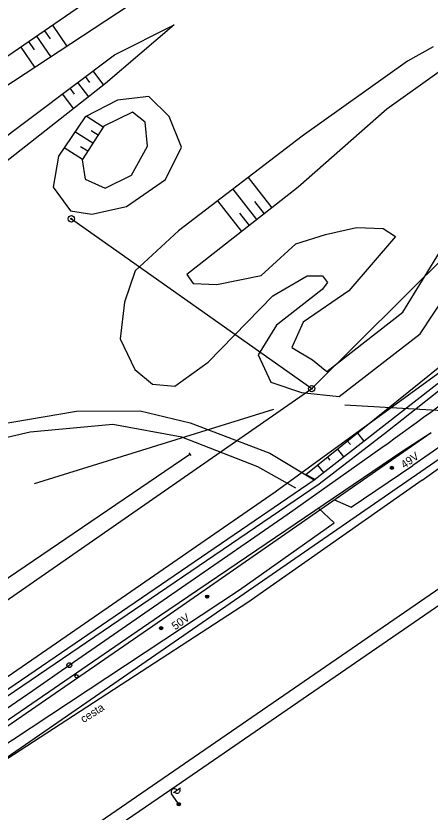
# Model space of a CAD drawing. Extents: x -469926 to -462499, y -1098642 to -1092733.
# Drawn here: x -466191.4 to -466126.7, y -1095960.6 to -1095836.3 of the extents above; entities that cross this region are included whole.
import ezdxf

# ---------------------------------------------------------------- set-up
doc = ezdxf.new("R2010")
doc.units = 0
for name, color, linetype in [('Vrstva 1', 7, 'Continuous'), ('Vrstva 10', 7, 'Continuous'), ('Vrstva 11', 7, 'Continuous'), ('Vrstva 13', 7, 'Continuous'), ('Vrstva 14', 7, 'Continuous'), ('Vrstva 24', 7, 'Continuous'), ('Vrstva 44', 7, 'Continuous'), ('Vrstva 48', 7, 'Continuous'), ('Vrstva 50', 7, 'Continuous'), ('Vrstva 6', 7, 'Continuous'), ('Vrstva 62', 7, 'Continuous'), ('Vrstva 8', 7, 'Continuous')]:
    doc.layers.add(name, color=color, linetype=linetype)

msp = doc.modelspace()

# ---------------------------------------------------------------- linework, layer by layer
at = {"layer": 'Vrstva 1'}
for p, q in [((-466145.15, -1095894.51), (-466082.34, -1095832.11)), ((-466145.15, -1095894.51), (-466082.34, -1095832.11)), ((-466182.7, -1095867.99), (-466145.15, -1095894.51)), ((-466207.82, -1095937.97), (-466145.15, -1095894.51)), ((-466207.82, -1095937.97), (-466145.15, -1095894.51))]:
    msp.add_line(p, q, dxfattribs=at)
for points in [[(-466210.14, -1095956.35), (-466188.73, -1095941.65), (-466183.02, -1095937.7), (-466170.53, -1095929.08), (-466148.98, -1095914.16), (-466134.33, -1095903.79)], [(-466724.57, -1096293.52), (-466714.37, -1096286.02), (-466704.21, -1096278.54), (-466695.06, -1096271.86), (-466685.62, -1096264.93), (-466671.16, -1096254.3), (-466659.11, -1096245.39), (-466634.9, -1096227.39), (-466620.02, -1096216.8), (-466602.98, -1096205), (-466568.99, -1096181.57), (-466522.69, -1096149.63), (-466496.45, -1096131.58), (-466439.19, -1096092.1), (-466394.38, -1096061.36), (-466347.94, -1096029.73), (-466315.43, -1096007.55), (-466259.5, -1095969.51), (-466164.18, -1095904.72)], [(-466200.77, -1095977.65), (-466186.05, -1095967.51), (-466178.22, -1095962.11), (-466097.13, -1095906.36)]]:
    msp.add_lwpolyline(points, dxfattribs=at)
msp.add_arc((-466398.56, -1095531.02), 456.92, 305.3291, 310.8345, dxfattribs=at)
at = {"layer": 'Vrstva 10'}
for p, q in [((-466101.5, -1095899.39), (-466139.97, -1095897.07)), ((-466188.47, -1095909.3), (-466151.05, -1095897.72))]:
    msp.add_line(p, q, dxfattribs=at)
for points in [[(-466169.44, -1095826.6), (-466206.83, -1095852.3), (-466241.68, -1095876.03), (-466204.38, -1095854.75), (-466166.51, -1095829.87)], [(-466257.17, -1095903.36), (-466258.01, -1095899), (-466253.85, -1095896.13), (-466249.92, -1095895.89), (-466243.68, -1095892.52), (-466216.94, -1095871.66), (-466195.35, -1095856.9), (-466175.95, -1095842.35), (-466166.66, -1095837.7), (-466177.39, -1095846.87), (-466196.94, -1095862.23), (-466215.42, -1095875.35), (-466231.4, -1095889.92), (-466244.34, -1095900.39), (-466247.67, -1095900.85), (-466250.08, -1095900.27), (-466252.75, -1095902), (-466255.04, -1095904.92)], [(-466185.67, -1095837.75), (-466183.44, -1095840.99)], [(-466186.91, -1095838.6), (-466186.02, -1095839.89)], [(-466189.38, -1095840.3), (-466188.51, -1095841.57)], [(-466188.14, -1095839.45), (-466185.95, -1095842.64)], [(-466190.61, -1095841.15), (-466188.46, -1095844.29)], [(-466179.33, -1095844.88), (-466177.67, -1095847.09)], [(-466180.53, -1095845.78), (-466179.86, -1095846.68)], [(-466182.92, -1095847.58), (-466182.24, -1095848.5)], [(-466181.73, -1095846.68), (-466180.03, -1095848.94)], [(-466184.12, -1095848.48), (-466182.39, -1095850.79)], [(-466177.72, -1095853.65), (-466180.39, -1095851.95)], [(-466179.34, -1095856.18), (-466182.14, -1095854.39)], [(-466178.53, -1095854.91), (-466179.6, -1095854.23)], [(-466180.95, -1095858.71), (-466183.81, -1095856.88)], [(-466180.14, -1095857.44), (-466181.26, -1095856.73)]]:
    msp.add_lwpolyline(points, dxfattribs=at)
at = {"layer": 'Vrstva 11'}
for p, q in [((-466132.86, -1095906.97), (-466132.54, -1095906.65)), ((-466132.73, -1095907.1), (-466132.41, -1095906.78)), ((-466161.72, -1095927.08), (-466161.39, -1095926.75)), ((-466161.59, -1095927.21), (-466161.26, -1095926.88)), ((-466168.91, -1095932.01), (-466168.59, -1095931.69)), ((-466168.78, -1095932.15), (-466168.46, -1095931.82))]:
    msp.add_line(p, q, dxfattribs=at)
for centre in [(-466132.63, -1095906.88), (-466161.48, -1095926.99), (-466168.68, -1095931.92)]:
    msp.add_circle(centre, 0.25, dxfattribs=at)
at = {"layer": 'Vrstva 13'}
for points in [[(-466000, -1095814.27), (-466009.79, -1095826.38), (-466022.25, -1095837.46), (-466044.21, -1095854.09), (-466061.58, -1095865.63), (-466069.9, -1095872.3), (-466072.6, -1095875.22), (-466084.54, -1095879.16), (-466099.65, -1095886.96), (-466116.56, -1095897.64), (-466129.35, -1095906.52)], [(-466127.89, -1095908.79), (-466114.73, -1095899.39), (-466097.6, -1095888.4), (-466082.79, -1095881.69), (-466077.6, -1095881.25), (-466073.44, -1095879.76), (-466077.1, -1095886.28), (-466075.51, -1095891.49)], [(-466127.89, -1095908.79), (-466114.73, -1095899.39), (-466097.6, -1095888.4), (-466082.79, -1095881.69), (-466077.6, -1095881.25), (-466073.44, -1095879.76), (-466077.1, -1095886.28), (-466075.51, -1095891.49)], [(-466374.19, -1096000), (-466332.05, -1095971.44), (-466298.9, -1095947.61), (-466243.94, -1095910.08), (-466240.17, -1095907.94), (-466235.57, -1095906.87), (-466228.22, -1095905.61), (-466216.23, -1095905.01), (-466194.51, -1095900.15), (-466181.92, -1095898.03), (-466171.97, -1095897.98), (-466164.14, -1095899.83), (-466151.71, -1095904.6), (-466144.76, -1095908.73)], [(-466147.65, -1095910.07), (-466153.55, -1095906.72), (-466165.44, -1095902.07), (-466176.22, -1095900.11), (-466189.12, -1095901.31), (-466205.11, -1095904.98), (-466217.1, -1095907.41), (-466223.08, -1095908.19), (-466229.62, -1095908.34), (-466235.8, -1095909.2), (-466240.59, -1095910.65), (-466246.26, -1095914.17), (-466297.93, -1095949.87), (-466329.85, -1095972.98), (-466369.94, -1096000)], [(-466141.59, -1095911.87), (-466138.97, -1095913.04), (-466129.35, -1095906.52)], [(-466141.59, -1095911.87), (-466138.97, -1095913.04), (-466129.35, -1095906.52)], [(-466141.59, -1095911.87), (-466138.97, -1095913.04), (-466129.35, -1095906.52)], [(-466127.89, -1095908.79), (-466155.15, -1095927.91), (-466196.99, -1095955.1), (-466229.43, -1095978.52)], [(-466230.73, -1095976.53), (-466197.96, -1095953.3), (-466156.42, -1095925.93), (-466141.63, -1095915.46), (-466144.1, -1095913.18)]]:
    msp.add_lwpolyline(points, dxfattribs=at)
at = {"layer": 'Vrstva 14'}
msp.add_circle((-466181.9, -1095939.43), 0.25, dxfattribs=at)
msp.add_circle((-466181.9, -1095939.43), 0.25, dxfattribs=at)
msp.add_circle((-466181.9, -1095939.43), 0.25, dxfattribs=at)
at = {"layer": 'Vrstva 24'}
for centre, radius in [((-466182.7, -1095867.99), 0.5), ((-466182.7, -1095867.99), 0.1), ((-466145.15, -1095894.51), 0.5), ((-466145.15, -1095894.51), 0.5), ((-466145.15, -1095894.51), 0.1), ((-466145.15, -1095894.51), 0.1)]:
    msp.add_circle(centre, radius, dxfattribs=at)
at = {"layer": 'Vrstva 44'}
for p, q in [((-466150.88, -1095910.6), (-466120.73, -1095888.71)), ((-466150.88, -1095910.6), (-466120.73, -1095888.71)), ((-466185.03, -1095934.22), (-466150.88, -1095910.6)), ((-466185.03, -1095934.22), (-466150.88, -1095910.6)), ((-466185.03, -1095934.22), (-466150.88, -1095910.6)), ((-466267.43, -1095990.87), (-466185.03, -1095934.22))]:
    msp.add_line(p, q, dxfattribs=at)
at = {"layer": 'Vrstva 48'}
for p, q in [((-466138, -1095901.45), (-466137, -1095902.69)), ((-466138, -1095901.45), (-466137, -1095902.69)), ((-466138, -1095901.45), (-466137, -1095902.69)), ((-466139.56, -1095902.7), (-466139.11, -1095903.25)), ((-466139.56, -1095902.7), (-466139.11, -1095903.25)), ((-466139.56, -1095902.7), (-466139.11, -1095903.25)), ((-466141.12, -1095903.96), (-466140.16, -1095905.15)), ((-466141.12, -1095903.96), (-466140.16, -1095905.15)), ((-466141.12, -1095903.96), (-466140.16, -1095905.15)), ((-466142.67, -1095905.21), (-466142.29, -1095905.69)), ((-466142.67, -1095905.21), (-466142.29, -1095905.69)), ((-466142.67, -1095905.21), (-466142.29, -1095905.69)), ((-466144.23, -1095906.47), (-466143.31, -1095907.6)), ((-466144.23, -1095906.47), (-466143.31, -1095907.6)), ((-466144.23, -1095906.47), (-466143.31, -1095907.6))]:
    msp.add_line(p, q, dxfattribs=at)
for points in [[(-466185.67, -1095837.75), (-466183.44, -1095840.99)], [(-466185.67, -1095837.75), (-466183.44, -1095840.99)], [(-466186.91, -1095838.6), (-466186.02, -1095839.89)], [(-466186.91, -1095838.6), (-466186.02, -1095839.89)], [(-466189.38, -1095840.3), (-466188.51, -1095841.57)], [(-466189.38, -1095840.3), (-466188.51, -1095841.57)], [(-466188.14, -1095839.45), (-466185.95, -1095842.64)], [(-466188.14, -1095839.45), (-466185.95, -1095842.64)], [(-466190.61, -1095841.15), (-466188.46, -1095844.29)], [(-466190.61, -1095841.15), (-466188.46, -1095844.29)], [(-466179.33, -1095844.88), (-466177.67, -1095847.09)], [(-466179.33, -1095844.88), (-466177.67, -1095847.09)], [(-466180.53, -1095845.78), (-466179.86, -1095846.68)], [(-466180.53, -1095845.78), (-466179.86, -1095846.68)], [(-466182.92, -1095847.58), (-466182.24, -1095848.5)], [(-466182.92, -1095847.58), (-466182.24, -1095848.5)], [(-466181.73, -1095846.68), (-466180.03, -1095848.94)], [(-466181.73, -1095846.68), (-466180.03, -1095848.94)], [(-466184.12, -1095848.48), (-466182.39, -1095850.79)], [(-466184.12, -1095848.48), (-466182.39, -1095850.79)], [(-466177.72, -1095853.65), (-466180.39, -1095851.95)], [(-466177.72, -1095853.65), (-466180.39, -1095851.95)], [(-466179.34, -1095856.18), (-466182.14, -1095854.39)], [(-466179.34, -1095856.18), (-466182.14, -1095854.39)], [(-466178.53, -1095854.91), (-466179.6, -1095854.23)], [(-466178.53, -1095854.91), (-466179.6, -1095854.23)], [(-466180.95, -1095858.71), (-466183.81, -1095856.88)], [(-466180.95, -1095858.71), (-466183.81, -1095856.88)], [(-466180.14, -1095857.44), (-466181.26, -1095856.73)], [(-466180.14, -1095857.44), (-466181.26, -1095856.73)], [(-466151.35, -1095866.26), (-466155.04, -1095861.52)], [(-466151.35, -1095866.26), (-466155.04, -1095861.52)], [(-466153.71, -1095868.1), (-466157.43, -1095863.34)], [(-466153.71, -1095868.1), (-466157.43, -1095863.34)], [(-466156.07, -1095869.95), (-466159.82, -1095865.16)], [(-466156.07, -1095869.95), (-466159.82, -1095865.16)], [(-466152.53, -1095867.18), (-466154.01, -1095865.28)], [(-466152.53, -1095867.18), (-466154.01, -1095865.28)], [(-466154.89, -1095869.03), (-466156.38, -1095867.11)], [(-466154.89, -1095869.03), (-466156.38, -1095867.11)]]:
    msp.add_lwpolyline(points, dxfattribs=at)
at = {"layer": 'Vrstva 50'}
msp.add_line((-466228.83, -1095976.93), (-466091.16, -1095881.95), dxfattribs=at)
at = {"layer": 'Vrstva 6'}
for p, q in [((-466166.75, -1095957.57), (-466165.67, -1095956.84)), ((-466166.75, -1095957.57), (-466165.67, -1095956.84)), ((-466166.05, -1095959.21), (-466167.04, -1095957.77)), ((-466166.05, -1095959.21), (-466167.04, -1095957.77)), ((-466166.07, -1095959.61), (-466165.99, -1095959.18)), ((-466166.07, -1095959.61), (-466165.99, -1095959.18)), ((-466165.89, -1095959.67), (-466165.8, -1095959.2)), ((-466165.89, -1095959.67), (-466165.8, -1095959.2))]:
    msp.add_line(p, q, dxfattribs=at)
for centre, radius in [((-466183.02, -1095937.7), 0.375), ((-466183.02, -1095937.7), 0.375), ((-466183.02, -1095937.7), 0.375), ((-466165.92, -1095959.42), 0.25), ((-466165.92, -1095959.42), 0.25), ((-466165.92, -1095959.42), 0.25), ((-466165.92, -1095959.42), 0.25)]:
    msp.add_circle(centre, radius, dxfattribs=at)
for centre, start, end in [((-466166.62, -1095957.49), 34.1697, 214.1697), ((-466166.62, -1095957.49), 34.1697, 214.1697), ((-466166.21, -1095957.21), 213.4671, 34.8723), ((-466166.21, -1095957.21), 213.4671, 34.8723)]:
    msp.add_arc(centre, 0.5, start, end, dxfattribs=at)
at = {"layer": 'Vrstva 62'}
msp.add_line((-466144.55, -1095908.75), (-466146.05, -1095907.93), dxfattribs=at)
msp.add_line((-466144.55, -1095908.75), (-466146.05, -1095907.93), dxfattribs=at)
msp.add_line((-466144.55, -1095908.75), (-466146.05, -1095907.93), dxfattribs=at)
msp.add_line((-466144.55, -1095908.75), (-466146.05, -1095907.93), dxfattribs=at)
msp.add_line((-466144.55, -1095908.75), (-466146.05, -1095907.93), dxfattribs=at)
msp.add_line((-466144.55, -1095908.75), (-466146.05, -1095907.93), dxfattribs=at)
for points in [[(-466146.05, -1095907.93), (-466101.27, -1095871.84), (-466070.19, -1095842.34), (-466041.53, -1095807.66), (-466020.37, -1095775.82), (-466000, -1095737.2)], [(-466144.76, -1095908.73), (-466099.57, -1095873.53), (-466068.63, -1095843.26), (-466040.48, -1095809.32), (-466019.38, -1095777.36), (-466000, -1095740.59)], [(-466133.31, -1095901.17), (-466099.47, -1095874.4), (-466068.13, -1095843.47), (-466039.87, -1095809.41), (-466018.38, -1095776.67), (-466000, -1095741.53)], [(-466126.18, -1095841.13), (-466130.2, -1095843.36), (-466146.62, -1095855.1), (-466165.98, -1095869.85), (-466172.75, -1095876.13), (-466174.4, -1095881), (-466175.09, -1095886.73), (-466172.79, -1095891.54), (-466170.03, -1095893.83), (-466166.53, -1095894.11), (-466161.34, -1095890.38), (-466151.21, -1095880.03), (-466145.83, -1095876.88), (-466143.45, -1095876.9), (-466142.68, -1095877.92), (-466143.53, -1095879.02), (-466150.65, -1095884.58), (-466153.51, -1095889.23), (-466151.54, -1095893.5), (-466146.74, -1095895.13), (-466140.85, -1095895.72), (-466128.21, -1095885.93), (-466121.8, -1095876.24)], [(-466126.18, -1095841.13), (-466130.2, -1095843.36), (-466146.62, -1095855.1), (-466165.98, -1095869.85), (-466172.75, -1095876.13), (-466174.4, -1095881), (-466175.09, -1095886.73), (-466172.79, -1095891.54), (-466170.03, -1095893.83), (-466166.53, -1095894.11), (-466161.34, -1095890.38), (-466151.21, -1095880.03), (-466145.83, -1095876.88), (-466143.45, -1095876.9), (-466142.68, -1095877.92), (-466143.53, -1095879.02), (-466150.65, -1095884.58), (-466153.51, -1095889.23), (-466151.54, -1095893.5), (-466146.74, -1095895.13), (-466140.85, -1095895.72), (-466128.21, -1095885.93), (-466121.8, -1095876.24)], [(-466615.6, -1096265.47), (-466583.43, -1096243.6), (-466541.63, -1096214.96), (-466495.34, -1096183.48), (-466451.83, -1096153.21), (-466395.24, -1096113.75), (-466338.99, -1096074.99), (-466284.5, -1096037.79), (-466252.35, -1096015.91), (-466228.8, -1095999.28), (-466166.33, -1095956.56), (-466074.59, -1095893.48)], [(-466681.99, -1096281.76), (-466661.3, -1096265.9), (-466636.93, -1096248.01), (-466586.97, -1096213.44), (-466544.14, -1096184), (-466498.15, -1096152.33), (-466446.33, -1096116.84), (-466393.88, -1096081.01), (-466339.22, -1096043.34), (-466296.16, -1096013.66), (-466251.05, -1095982.55), (-466210.37, -1095954.49), (-466144, -1095909.4), (-466133.31, -1095901.17)], [(-466546.99, -1096190.64), (-466541.08, -1096186.48), (-466495.03, -1096153.99), (-466442.96, -1096118.49), (-466391.63, -1096083.13), (-466339.37, -1096047.17), (-466296.23, -1096017.37), (-466250.63, -1095985.97), (-466208.04, -1095956.82), (-466168.92, -1095929.97), (-466131.07, -1095904.3), (-466126.49, -1095901.37)], [(-466540.52, -1096187.38), (-466493.81, -1096154.32), (-466442.18, -1096119.55), (-466390.63, -1096083.17), (-466337.39, -1096046.71), (-466295.63, -1096018.03), (-466249.77, -1095986.51), (-466207.26, -1095957.21), (-466168.48, -1095930.53), (-466126.49, -1095901.37)], [(-466637.57, -1096247.89), (-466587.71, -1096212.89), (-466544.93, -1096183.51), (-466498.54, -1096151.83), (-466446.87, -1096116.21), (-466393.85, -1096080.09), (-466339.66, -1096042.67), (-466297.03, -1096013.11), (-466251.59, -1095981.86), (-466211.27, -1095954.14), (-466144.76, -1095908.73)]]:
    msp.add_lwpolyline(points, dxfattribs=at)
for points in [[(-466142.78, -1095891.81), (-466130.93, -1095882.58), (-466124.77, -1095872.56), (-466109.27, -1095858.37), (-466107.89, -1095854.99), (-466109.01, -1095852.04), (-466114.14, -1095848.46), (-466120.63, -1095844.74), (-466125.23, -1095845.05), (-466133.4, -1095850.85), (-466147.26, -1095863.06), (-466164.68, -1095876.68), (-466163.66, -1095878.1), (-466159.96, -1095878.22), (-466153.02, -1095876.84), (-466147.61, -1095871.9), (-466142.99, -1095870.41), (-466138.17, -1095869.36), (-466133.97, -1095869.48), (-466132.04, -1095870.72), (-466139.36, -1095879.21), (-466146.46, -1095884.15), (-466148.25, -1095888.1), (-466145, -1095889.99)], [(-466142.78, -1095891.81), (-466130.93, -1095882.58), (-466124.77, -1095872.56), (-466109.27, -1095858.37), (-466107.89, -1095854.99), (-466109.01, -1095852.04), (-466114.14, -1095848.46), (-466120.63, -1095844.74), (-466125.23, -1095845.05), (-466133.4, -1095850.85), (-466147.26, -1095863.06), (-466164.68, -1095876.68), (-466163.66, -1095878.1), (-466159.96, -1095878.22), (-466153.02, -1095876.84), (-466147.61, -1095871.9), (-466142.99, -1095870.41), (-466138.17, -1095869.36), (-466133.97, -1095869.48), (-466132.04, -1095870.72), (-466139.36, -1095879.21), (-466146.46, -1095884.15), (-466148.25, -1095888.1), (-466145, -1095889.99)], [(-466180.56, -1095852.03), (-466184.7, -1095858.2), (-466185.52, -1095863.05), (-466182.81, -1095866.72), (-466179.5, -1095867.27), (-466174.07, -1095866.05), (-466167.99, -1095861.85), (-466165.51, -1095856.81), (-466167.4, -1095851.99), (-466170.58, -1095848.86), (-466175.49, -1095849.43)], [(-466181.01, -1095858.79), (-466180.55, -1095861.8), (-466177.43, -1095863.18), (-466173.29, -1095861.19), (-466170.78, -1095856.66), (-466171.15, -1095852.91), (-466173.15, -1095851.32), (-466177.64, -1095853.52)]]:
    msp.add_lwpolyline(points, close=True, dxfattribs=at)
at = {"layer": 'Vrstva 8'}
for p, q in [((-466164.32, -1095904.51), (-466164.05, -1095904.93)), ((-466164.32, -1095904.51), (-466164.05, -1095904.93)), ((-466164.32, -1095904.51), (-466164.05, -1095904.93)), ((-466164.18, -1095904.72), (-466164.18, -1095904.72)), ((-466164.18, -1095904.72), (-466164.18, -1095904.72)), ((-466164.18, -1095904.72), (-466164.18, -1095904.72))]:
    msp.add_line(p, q, dxfattribs=at)

# ---------------------------------------------------------------- texts
at = {"layer": 'Vrstva 11'}
for s, p in [('49V', (-466130.69, -1095907.05)), ('50V', (-466166.49, -1095932.27))]:
    msp.add_text(s, height=1.25, rotation=35.0887, dxfattribs=at).set_placement(p)
at = {"layer": 'Vrstva 13'}
msp.add_text('cesta', height=1.25, rotation=32.3277, dxfattribs=at).set_placement((-466180.79, -1095946.76))

doc.saveas('drawing.dxf')
